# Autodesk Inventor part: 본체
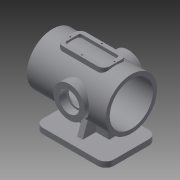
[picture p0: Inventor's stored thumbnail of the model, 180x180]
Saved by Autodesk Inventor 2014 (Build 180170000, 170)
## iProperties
Created: 2021-11
Part Number: 본체
Material: Generic
Document SubType Name: Modeling
Designer: kb542
Density: 1 g/cm^3
Appearance: Default
Author: kb542
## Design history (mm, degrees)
sketch "스케치1"
  geometry: L1 (0, 0)-(210, 0); L2 (0, 32.5)-(0, 47.5); L3 (0, 47.5)-(10, 47.5); L4 (10, 47.5)-(10, 65); L5 (10, 65)-(210, 65); L6 (210, 65)-(210, 55); L7 (0, 32.5)-(25, 32.5); L8 (25, 32.5)-(25, 55); L9 (25, 55)-(210, 55)
  constraints: 18 end point, 4 perpendicular, 3 parallel, 2 vertical alignment, 1 horizontal
  dimensions: "d0" = 210 distance of L1.start L1.end; "d1" = 130 diameter of L5 L1; "d2" = 95 diameter of L3 L1; "d3" = 10 distance of L2.end L3.end; "d44" = 65 diameter of L7 L1; "d45" = 110 diameter of L9 L1; "d46" = 25 distance of L2.start L7.end
revolve "회전1" sketch "스케치1" stored, may be unused: angle "d4" = 90 deg
node "작업 평면2"
sketch "스케치3"
  geometry: L1 (50, 65)-(190, 65); L2 (210, 45)-(210, -45); L3 (190, -65)-(50, -65); L4 (30, -45)-(30, 45); L5 (0, -47.5)-(0, 47.5) reference; A1 r 20 centre (50, 45) between (50, 65) and (30, 45); A2 r 20 centre (190, 45) between (210, 45) and (190, 65); A3 r 20 centre (190, -45) between (190, -65) and (210, -45); A4 r 20 centre (50, -45) between (30, -45) and (50, -65); 6 further points
  constraints: 8 end point, 8 point on circle, 8 tangent, 6 point on line, 4 centre point, 3 equal radius, 2 midpoint, 2 parallel, 1 horizontal, 1 horizontal alignment, 1 perpendicular
  dimensions: "d12" = 180 distance of point (30, 65) point (210, 65); "d13" = 130 distance of point (30, -65) point (30, 65); "d14" = 30 distance between parallel lines of L4 L5; "d15" = 20 radius of A1
extrude "돌출2" join sketch "스케치3" distance "d16" = 14; taper "d17" = 0 deg
node "작업 평면3"
sketch "스케치4"
  geometry: L1 (65, 30)-(155, 30); L2 (170, 15)-(170, -15); L3 (155, -30)-(65, -30); L4 (50, -15)-(50, 15); L5 (0, -47.5)-(0, 47.5) reference; L6 (155, 20)-(65, 20); L7 (60, 15)-(60, -15); L8 (65, -20)-(155, -20); L9 (160, -15)-(160, 15); A1 r 15 centre (65, 15) between (65, 30) and (50, 15); A2 r 15 centre (65, -15) between (50, -15) and (65, -30); A3 r 15 centre (155, -15) between (155, -30) and (170, -15); A4 r 15 centre (155, 15) between (170, 15) and (155, 30); A5 r 5 centre (65, 15) between (65, 20) and (60, 15); A6 r 5 centre (65, -15) between (60, -15) and (65, -20); A7 r 5 centre (155, -15) between (155, -20) and (160, -15); A8 r 5 centre (155, 15) between (160, 15) and (155, 20); 6 further points
  constraints: 16 end point, 16 point on circle, 16 tangent, 8 centre point, 6 equal radius, 6 point on line, 4 parallel, 2 midpoint, 2 perpendicular, 1 horizontal, 1 horizontal alignment, 3 other
  dimensions: "d19" = 50 distance between parallel lines of L4 L5; "d20" = 120 distance of point (50, 30) point (170, 30); "d21" = 60 distance of point (50, -30) point (50, 30); "d22" = 10 distance between parallel lines of L6 L1; "d23" = 15 radius of A1; "d24" = 5 radius of A5
extrude "돌출3" join sketch "스케치4" stored distance "d25" = 14; taper "d26" = 0 deg
node "작업 평면4"
sketch "스케치5"
  geometry: L1 (14, 0)-(14, 90) reference; L2 (14, 90)-(14, 110) reference; L3 (14, -20)-(14, 0) reference; L4 (54.476, 71.112)-(14, 85.844); L5 (54.476, 18.888)-(14, 4.156); L6 (114, 45)-(49, 45); A1 r 65 centre (114, 45) between (54.476, 71.112) and (49, 45) reference; 1 further point
  constraints: 6 end point, 3 point on circle, 2 point on line, 1 perpendicular, 1 other
  dimensions: "d27" = 110 deg angle of L3 L5
extrude "돌출4" join sketch "스케치5" stored distance "d28" = 14; taper "d29" = 0 deg
node "작업 평면5"
sketch "스케치6"
  geometry: L1 (-40, -49)-(160, -49) reference; L2 (0, -14)-(140, -14) reference; L3 (99.017, -46.042)-(109.734, -16.597); L4 (24.644, -43.504)-(16.379, -20.799); 1 further point
  constraints: 4 end point
  dimensions: "d30" = 110 deg angle of L2 L4; "d31" = 110 deg angle of L2 L3
feature "리브1" dims "d32" = 1, "d33" = 14, "d34" = 0, "d35" = 0, "d36" = 1, "d37" = 1
feature "리브2" dims "d38" = 1, "d39" = 14, "d40" = 0, "d41" = 0, "d42" = 1, "d43" = 1
node "작업 평면7"
sketch "스케치15"
  geometry: C1 r 40 at (127, 0); 1 further point
  constraints: 1 centre point, 1 horizontal alignment
  dimensions: "d61" = 80 diameter of C1; "d62" = 127 distance of C1.centre point (0, 0)
extrude "돌출6" join sketch "스케치15" stored distance "d63" = 14; taper "d64" = 0 deg
sketch "스케치16"
  geometry: C1 r 40 at (0, 0) reference; 2 further points
  constraints: 1 coincident
hole "구멍2" sketch "스케치16" at (0, 0) diameter "d65" = 42; stored, may be unused: countersink angle "d69" = 90 deg, drill point angle "d71" = 118 deg; dims "d66" = 6, "d67" = 52, "d68" = 19, "d70" = 8
sketch "스케치17"
  geometry: C1 r 40 at (0, 0) reference; A1 r 32.5 centre (0, 0) between (0, 32.5) and (-32.5, 0); 3 further points
  constraints: 4 point on circle, 1 centre point, 1 coincident
  dimensions: "d72" = 65 diameter of A1
hole "구멍3" sketch "스케치17" at (0, 32.5), (-32.5, 0), (32.5, 0), (0, -32.5) diameter "d73" = 3.242; stored, may be unused: countersink angle "d77" = 90 deg, drill point angle "d79" = 118 deg; dims "d74" = 11, "d75" = 52, "d76" = 19, "d78" = 13
sketch "스케치18"
  geometry: C1 r 47.5 at (0, 0) reference; A1 r 40 centre (0, 0) between (40, 0) and (0, -40); 2 further points
  constraints: 4 point on circle, 1 centre point, 1 concentric
  dimensions: "d80" = 80 diameter of A1
hole "구멍4" sketch "스케치18" at (40, 0), (0, -40), (-40, 0), (0, 40) diameter "d81" = 3.242; stored, may be unused: countersink angle "d85" = 90 deg, drill point angle "d87" = 118 deg; dims "d82" = 11, "d83" = 52, "d84" = 19, "d86" = 13
sketch "스케치19"
  geometry: L1 (60, -15)-(60, 15) reference; L2 (65, 30)-(155, 30) reference; L3 (110, 25)-(110, -25); 8 further points
  constraints: 3 midpoint, 2 coincident, 2 end point, 1 horizontal alignment, 1 perpendicular, 1 vertical alignment
  dimensions: "d88" = 50 distance of L3.start L3.end; "d89" = 55 distance of point (110, 0) point (55, 0); "d90" = 55 horizontal distance of point (165, 1.927) point (110, 0)
hole "구멍5" sketch "스케치19" at (110, 25), (110, -25), (55, 0), (165, 1.927) diameter "d91" = 3.242; stored, may be unused: countersink angle "d95" = 90 deg, drill point angle "d97" = 118 deg; dims "d92" = 9, "d93" = 52, "d94" = 19, "d96" = 11
sketch "스케치20"
  geometry: 1 further point
node "솔리드1"
mirror "대칭2"
other parameters: "d11" = -114, "d60" = -75
